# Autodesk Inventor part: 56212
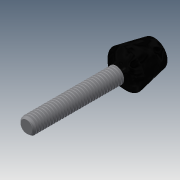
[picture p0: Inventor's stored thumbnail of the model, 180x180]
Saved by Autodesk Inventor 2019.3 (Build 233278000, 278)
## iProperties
Created: 2011-12
Part Number: 56212
Material: Ogólny
Document SubType Name: Modeling
Designer: CADENGINEERING4
Density: 1 g/cm^3
Appearance: Domyślna
Author: CADENGINEERING4
Revision Number: ÈÎºÎ
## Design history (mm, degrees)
feature "Ðý×ª2"
node "Bryła1"
